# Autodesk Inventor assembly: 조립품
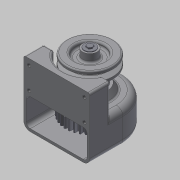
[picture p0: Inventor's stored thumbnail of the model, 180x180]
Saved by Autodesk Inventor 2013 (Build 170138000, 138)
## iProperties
Created: 2015-02
Part Number: 조립품
Document SubType Name: Assembly
Designer: Administrator
Author: Administrator
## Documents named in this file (14)
- C:\Users\Administrator\Desktop\450216V1015\조립품.iam
- C:\Users\Administrator\Desktop\450216V1015\본체.ipt
- C:\Users\Administrator\Desktop\450216V1015\축.ipt
- C:\Users\Administrator\Desktop\450216V1015\오일실.ipt
- C:\Users\Administrator\Desktop\450216V1015\베어링 6001.ipt
- C:\Users\Administrator\Desktop\450216V1015\M3x0.5.ipt
- C:\Users\Administrator\Desktop\450216V1015\축커버.ipt
- C:\Users\Administrator\Desktop\450216V1015\키5x5.ipt
- C:\Users\Administrator\Desktop\450216V1015\스퍼기어.ipt
- C:\Users\Administrator\Desktop\450216V1015\키4x4.ipt
- C:\Users\Administrator\Desktop\450216V1015\V-벨트풀리.ipt
- C:\Users\Administrator\Desktop\450216V1015\M5x0.8.ipt
- M5x0.8.ipt
- C:\Users\Administrator\Desktop\450216V1015\와샤.ipt
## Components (6 placed, 3 different names)
1. V-벨트풀리:1 — 각도:4, 플러쉬:1, 각도:5
2. M5x0.8:1 — 각도:5
3. M3x0.5:1
4. M3x0.5:2
5. M3x0.5:3
6. M3x0.5:4
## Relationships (3: Angle 2, Flush 1)
- 각도:4 [Angle]: V-벨트풀리:1
- 플러쉬:1 [Flush]: V-벨트풀리:1
- 각도:5 [Angle]: V-벨트풀리:1 ↔ M5x0.8:1
